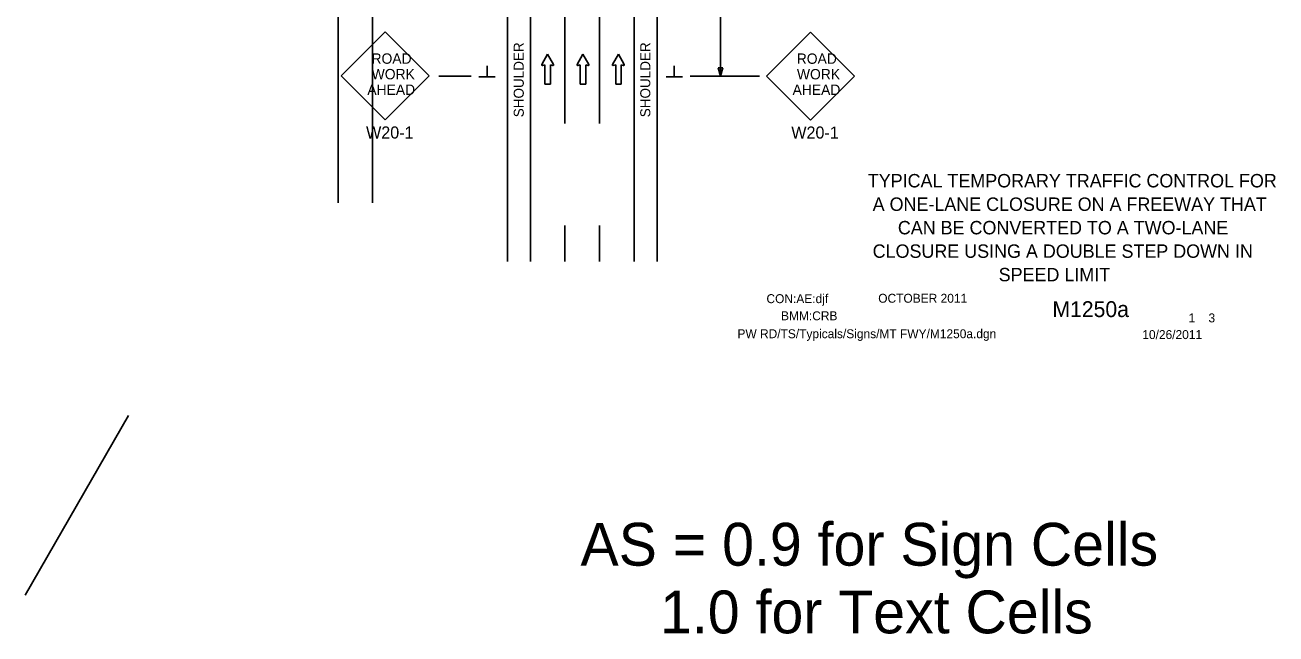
# Model space of a CAD drawing. Extents: x 16576 to 19508, y 5728 to 6974.
# Drawn here: x 16576 to 17444, y 5728 to 6151 of the extents above; entities that cross this region are included whole.
import ezdxf

# ---------------------------------------------------------------- set-up
doc = ezdxf.new("R2010")
doc.units = 0
for name, color, linetype in [('ALI_LEGAL_EX', 7, 'Continuous'), ('BORDER', 7, 'Continuous'), ('BORDER_SIGNAL_WO', 7, 'Continuous'), ('MT_SCRATCH_LEVEL_E', 7, 'Continuous'), ('PAVT_EDGE_EX', 7, 'Continuous'), ('TRAFFIC_SIGNS_PR', 7, 'Continuous'), ('TYPICAL_TEXT_DIMEN_PR', 7, 'Continuous')]:
    doc.layers.add(name, color=color, linetype=linetype)

msp = doc.modelspace()

# ---------------------------------------------------------------- linework, layer by layer
at = {"layer": 'ALI_LEGAL_EX'}
for p, q in [((16950.77, 6911.88), (16950.77, 6082.69)), ((16974.77, 6911.88), (16974.77, 6082.69)), ((16793.2, 6891.57), (16793.2, 6027.66)), ((16817.2, 6891.57), (16817.2, 6027.66))]:
    msp.add_line(p, q, dxfattribs=at)
for points in [[(16950.77, 6086.88), (16950.77, 6111.88)], [(16950.77, 6086.88), (16950.77, 6111.88)], [(16974.77, 6111.88), (16974.77, 6086.88)], [(16950.77, 5986.88), (16950.77, 6011.88)], [(16950.77, 5986.88), (16950.77, 6011.88)], [(16974.77, 6011.88), (16974.77, 5986.88)]]:
    msp.add_lwpolyline(points, dxfattribs=at)
at = {"layer": 'MT_SCRATCH_LEVEL_E'}
for p, q in [((16938.74, 6131.01), (16934.63, 6123.77)), ((16935.11, 6123.08), (16936.89, 6123.4)), ((16936.89, 6123.4), (16936.89, 6110.14)), ((16942.89, 6123.77), (16938.74, 6131.01)), ((16940.63, 6110.14), (16940.63, 6123.4)), ((16940.63, 6123.4), (16942.41, 6123.08)), ((16963.3, 6131.01), (16959.19, 6123.77)), ((16959.67, 6123.08), (16961.45, 6123.4)), ((16961.45, 6123.4), (16961.45, 6110.14)), ((16967.44, 6123.77), (16963.3, 6131.01)), ((16965.19, 6110.14), (16965.19, 6123.4)), ((16965.19, 6123.4), (16966.97, 6123.08)), ((16987.86, 6131.01), (16983.75, 6123.77)), ((16984.23, 6123.08), (16986.01, 6123.4)), ((16986.01, 6123.4), (16986.01, 6110.14)), ((16992, 6123.77), (16987.86, 6131.01)), ((16989.75, 6110.14), (16989.75, 6123.4)), ((16989.75, 6123.4), (16991.53, 6123.08)), ((16936.89, 6110.14), (16940.63, 6110.14)), ((16961.45, 6110.14), (16965.19, 6110.14)), ((16986.01, 6110.14), (16989.75, 6110.14))]:
    msp.add_line(p, q, dxfattribs=at)
for centre, start, end in [((16935.04, 6123.54), 150.42484, 279.96381), ((16942.48, 6123.54), 260.03619, 29.77312), ((16959.59, 6123.54), 150.42484, 279.96381), ((16967.04, 6123.54), 260.03619, 29.77312), ((16984.15, 6123.54), 150.42484, 279.96381), ((16991.59, 6123.54), 260.03619, 29.77312)]:
    msp.add_arc(centre, 0.463, start, end, dxfattribs=at)
at = {"layer": 'PAVT_EDGE_EX'}
for p, q in [((16910.77, 6923.28), (16910.77, 5986.88)), ((16926.77, 6923.28), (16926.77, 5986.88)), ((16998.77, 6923.28), (16998.77, 5986.88)), ((17014.77, 6923.28), (17014.77, 5986.88))]:
    msp.add_line(p, q, dxfattribs=at)
at = {"layer": 'TRAFFIC_SIGNS_PR'}
for p, q in [((16825.99, 6146.32), (16795.44, 6115.77)), ((16856.53, 6115.77), (16825.99, 6146.32)), ((17121.23, 6146.28), (17090.68, 6115.74)), ((17151.78, 6115.74), (17121.23, 6146.28)), ((16795.44, 6115.77), (16825.99, 6085.22)), ((16825.99, 6085.22), (16856.53, 6115.77)), ((17090.68, 6115.74), (17121.23, 6085.19)), ((17121.23, 6085.19), (17151.78, 6115.74))]:
    msp.add_line(p, q, dxfattribs=at)
at = {"layer": 'TYPICAL_TEXT_DIMEN_PR'}
for p, q in [((17058.77, 6205.62), (17058.77, 6115.62)), ((16885.71, 6115.62), (16863.25, 6115.62)), ((16902.28, 6115.12), (16891.03, 6115.12)), ((16896.65, 6115.12), (16896.65, 6122.9)), ((17032.33, 6115.12), (17021.08, 6115.12)), ((17026.7, 6115.12), (17026.7, 6122.9)), ((17037.77, 6115.62), (17085.95, 6115.62)), ((17058.77, 6115.62), (17057.2, 6121.48)), ((17057.2, 6121.48), (17058.77, 6121.48)), ((17058.77, 6121.48), (17060.34, 6121.48)), ((17060.34, 6121.48), (17058.77, 6115.62)), ((16647.75, 5880), (16575.89, 5755.4))]:
    msp.add_line(p, q, dxfattribs=at)

# ---------------------------------------------------------------- texts
at = {"layer": 'BORDER'}
for s, p in [('TYPICAL TEMPORARY TRAFFIC CONTROL FOR', (17161.04, 6038.42)), ('A ONE-LANE CLOSURE ON A FREEWAY THAT', (17164.42, 6022.12)), ('CAN BE CONVERTED TO A TWO-LANE ', (17181.92, 6005.82)), ('CLOSURE USING A DOUBLE STEP DOWN IN ', (17164.42, 5989.52)), ('SPEED LIMIT', (17251.92, 5973.22))]:
    msp.add_text(s, height=9.3, dxfattribs=at).set_placement(p)
at = {"layer": 'BORDER_SIGNAL_WO'}
for s, height, p in [('CON:AE:djf  ', 6.2, (17090.69, 5958.06)), ('    OCTOBER 2011    ', 6.2, (17159.08, 5958.34)), ('    M1250a   ', 11, (17272.86, 5948.38)), ('BMM:CRB   ', 6.2, (17100.81, 5946.17)), (' 1    3 ', 6.2, (17381.45, 5944.7)), ('PW RD/TS/Typicals/Signs/MT FWY/M1250a.dgn      ', 6.2, (17070.55, 5933.71)), ('10/26/2011    ', 6.2, (17351.65, 5933.13)), ('AS = 0.9 for Sign Cells', 29.7271, (16961.58, 5775.8)), ('     1.0 for Text Cells', 29.7271, (16961.58, 5728.8))]:
    msp.add_text(s, height=height, dxfattribs=at).set_placement(p)
at = {"layer": 'TRAFFIC_SIGNS_PR'}
for s, height, p in [('ROAD', 7.2, (16816.47, 6124.25)), ('ROAD', 7.2, (17111.72, 6124.21)), ('WORK', 7.2, (16816.59, 6113.45)), ('WORK', 7.2, (17111.84, 6113.41)), ('AHEAD', 7.2, (16813.57, 6102.65)), ('AHEAD', 7.2, (17108.81, 6102.61)), ('W20-1', 8.37, (16812.68, 6072.35)), ('W20-1', 8.37, (17107.92, 6072.32))]:
    msp.add_text(s, height=height, dxfattribs=at).set_placement(p)
at = {"layer": 'TYPICAL_TEXT_DIMEN_PR'}
for p in [(16922.19, 6087.12), (17010.05, 6087.12)]:
    msp.add_text('SHOULDER', height=7, rotation=90, dxfattribs=at).set_placement(p)

doc.saveas('drawing.dxf')
